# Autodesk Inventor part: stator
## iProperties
Company: R&F Broers
Created: 2006-01
Part Number: stator
Document SubType Name: Modeling
Designer: Robbert
Manufacturer: Standard
Standards Organization: Custom
Project: ventilator
User Status: gereed
Author: Robbert Timmer
Title: ventilatorhuis
Subject: ventilator
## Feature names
1. Extrusion1
2. Extrusion2
3. Extrusion4
4. Revolution1
5. Extrusion3
6. Circular Pattern1
7. Circular Pattern2
8. Fillet1
